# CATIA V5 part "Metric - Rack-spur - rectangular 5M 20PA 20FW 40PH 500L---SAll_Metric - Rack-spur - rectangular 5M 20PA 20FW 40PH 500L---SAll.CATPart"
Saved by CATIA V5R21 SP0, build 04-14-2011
Part number: Metric - Rack-spur - rectangular 5M 20PA 20FW 40PH 500L---SAll_Metric - Rack-spur - rectangular 5M 20PA 20FW 40PH 500L---SAll
Revision: ANY
Definition: UNKNOWN
Nomenclature: Metric - Rack-spur - rectangular 5M 20PA 20FW 40PH 500L---SAll_Metric - Rack-spur - rectangular 5M 20PA 20FW 40PH 500L---SAll
Source: Unknown
Material "Gold Metal": density 7860 kg/m3, Young's modulus 2e+11 Pa, Poisson ratio 0.266
Bounding box of the stored display mesh (mm): x 0 to 500, y 0 to 45, z -20 to 0
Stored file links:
  F:\catia world\MY WORK\rack and pinion\Metric - Rack-spur - rectangular 5M 20PA 20FW 40PH 500L---SAll_Metric - Rack-spur - rectangular 5M 20PA 20FW 40PH 500L---SAll.CATPart
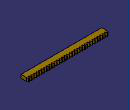
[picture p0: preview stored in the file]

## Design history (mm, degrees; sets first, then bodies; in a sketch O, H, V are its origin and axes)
Body1 "TeethCuts" (main body), material "Gold Metal"
  Solid1: solid without history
